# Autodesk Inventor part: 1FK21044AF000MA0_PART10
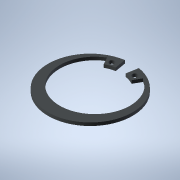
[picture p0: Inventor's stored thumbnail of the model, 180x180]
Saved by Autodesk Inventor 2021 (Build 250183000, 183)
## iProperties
Created: 2025-04
Part Number: 1FK21044AF000MA0_PART10
Material: Generic
Catalog Web Link: www.3dfindit.com
Description: -Servo synchronous motor
Document SubType Name: Modeling
Designer: psAdmin
Mass: 0.642463 g
Surface Area: 12.3927 cm^2
Volume: 0.642463 cm^3
Density: 1 g/cm^3
Appearance: PSOLRGB-212-217-219
Category: PARTsolutions
Title: 1FK21044AF000MA0_PART10
Author: Cadenas PARTsolutions
Comments: Servo synchronous motor
Sending System: PARTsolutions
Preprocessor: ST-DEVELOPER v19.3
PSOL_IDENT_0: {$CADENAS_DATA/23d-libs/siemens_ag/_cat_/39/c4/1fk21044af000ma0.prj},216 {VTYP=3D},{NB=1FK21044AF000
PSOL_IDENT_1: MA0_PART10},{LINA=1FK21044AF000MA0_PART10},{NN=1FK21044AF000MA0_PART10},{NOPRJ=TRUE},{DATE=19.08.202
PSOL_IDENT_2: 5 14:00:33},{GEOMDATE=30.07.2025 02:02:22},{VERSION=},{LINEID=10},{WBVAR=},{WBNUMERIC=}  {NB=1FK2104
PSOL_IDENT_3: 4AF000MA0_PART10},{LINA=1FK21044AF000MA0_PART10},{KT=DUMMY},{PREVIEW=../../../_pool_/cb/72/p_d211_xx
PSOL_IDENT_4: _00434j.png},{DESCSHORT=SIMOTICS S-1FK2 HD, SINAMICS S210 3AC 400V-480V, 1.27 Nm, 3000 rpm},{DESCLON
PSOL_IDENT_5: G=SIMOTICS S-1FK2 HD servo motor M0=1.27 Nm; PN = 0.4 kW at nN=3000 rpm (380-480 V); PN = 0.2 kW at
PSOL_IDENT_6: nN=1500 rpm (200-240 V); degree of protection IP64; cylindrical shaft D19x40mm; absolute encoder 22-
PSOL_IDENT_7: bit + 12-bit multiturn (encoder AM22DQC); with OCC interface; plug size M17, rotatable; SIMOTICS S-1
PSOL_IDENT_8: FK2 servomotorfor a wide range of uses in industrial environments. SIMOTICS S‑1FK2 servomotors are c
PSOL_IDENT_9: ompact synchronous motors with a high dynamic performance that set themselves apart as a result of t
PSOL_IDENT_10: heir high power density, degree of protection and overload capability. The motors are available in t
PSOL_IDENT_11: wo variants: as High Dynamic variant (highest dynamic performance as a result of the low intrinsic m
PSOL_IDENT_12: oment of inertia for applications demanding a high dynamic performance with low moved masses) - and
PSOL_IDENT_13: as Compact variant (precise and stable closed-loop control for medium up to large moved masses as a
PSOL_IDENT_14: result of a medium intrinsic moment of inertia). SIMOTICSS‑1FK2 servomotors fully exploit their stre
PSOL_IDENT_15: ngths in a system with the SINAMICSS210 frequency converter and simple connection using the one cabl
PSOL_IDENT_16: e connection (OCC). Advantages include the short control and positioning times, fast and precise cor
PSOL_IDENT_17: rection of disturbing quantities as well as stable control with a high dynamic performance. The serv
PSOL_IDENT_18: o motors can be configured to address a wide range of requirements. For example with and without hol
PSOL_IDENT_19: ding brake, IP64 or IP65 degree of protection, singleturn or multiturn absolute encoders - to name j
PSOL_IDENT_20: ust a few. Further, the servomotors are available in different shaft heights extending from 20 to 10
PSOL_IDENT_21: 0. A shaft sealing ring is available to achieve an IP65 degree of protection and for subsequent moun
PSOL_IDENT_22: ting at the motor or as spare part. SIMOTICS - the optimum motor for each and every motion control a
PSOL_IDENT_23: pplication.},{INTNO=804766906428},{SUPPLIERALTNO=1FK2104-4AF00-0MA0},{MANUID=1FK21044AF000MA0},{MANU
PSOL_IDENT_24: NAME=Siemens},{MANUTYPEDESC=Synchronous motor 1FK2-HD 1.27 NM},{AAU732=SIMOTICS},{AAO057=S-1FK2},{AA
PSOL_IDENT_25: U734=SIMOTICS S-1FK2 HD servo motor M0=1.27 Nm; PN = 0.4 kW at nN=3000 rpm (380-480 V); PN = 0.2 kW
PSOL_IDENT_26: at nN=1500 rpm (200-240 V); degree of protection IP64; cylindrical shaft D19x40mm; absolute encoder
PSOL_IDENT_27: 22-bit + 12-bit multiturn (encoder AM22DQC); with OCC interface; plug size M17, rotatable;},{AAW338=
PSOL_IDENT_28: Synchronous motor 1FK2-HD 1.27 NM},{AAO742=SIMOTICS},{AAO663=4042948693322},{NOCUPEROU=1},{PRICEQUAN
PSOL_IDENT_29: TITY=1},{QUANTITYMIN=1},{QUANTITYINT=1},{CTN=85015100},{COO=DE},{AAO676=1FK2104-4AF00-0MA0},{AAO677=
PSOL_IDENT_30: Siemens AG},{ORDERUNIT=C62},{CONTENTUNIT=C62}
NB: 1FK21044AF000MA0_PART10
NT: Servo synchronous motor
NBSYN: $MANUID._PART10
LINA: 1FK21044AF000MA0_PART10
CATALOG: SIEMENS
PREVIEW: ../../../_pool_/cb/72/p_d211_xx_00434j.png
DESCSHORT: SIMOTICS S-1FK2 HD, SINAMICS S210 3AC 400V-480V, 1.27 Nm, 3000 rpm
DESCLONG: SIMOTICS S-1FK2 HD servo motor M0=1.27 Nm; PN = 0.4 kW at nN=3000 rpm (380-480 V); PN = 0.2 kW at nN=1500 rpm (200-240 V); degree of protection IP64; cylindrica
INTNO: 804766906428
SUPPLIERALTNO: 1FK2104-4AF00-0MA0
MANUID: 1FK21044AF000MA0
MANUNAME: Siemens
MANUTYPEDESC: Synchronous motor 1FK2-HD 1.27 NM
AAU732: SIMOTICS
AAO057: S-1FK2
AAU734: SIMOTICS S-1FK2 HD servo motor M0=1.27 Nm; PN = 0.4 kW at nN=3000 rpm (380-480 V); PN = 0.2 kW at nN=1500 rpm (200-240 V); degree of protection IP64; cylindrica
AAW338: Synchronous motor 1FK2-HD 1.27 NM
AAO742: SIMOTICS
AAO663: 4042948693322.0
NOCUPEROU: 1
PRICEQUANTITY: 1
QUANTITYMIN: 1
QUANTITYINT: 1
CTN: 85015100
COO: DE
ARTICLENO: 1FK21044AF000MA0_PART10
BOMINFO: 1FK21044AF000MA0_PART10
CREATOR: CADENAS GmbH
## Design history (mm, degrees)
feature "2025_04_17_15_01_28_0038"
body "Solid1"
